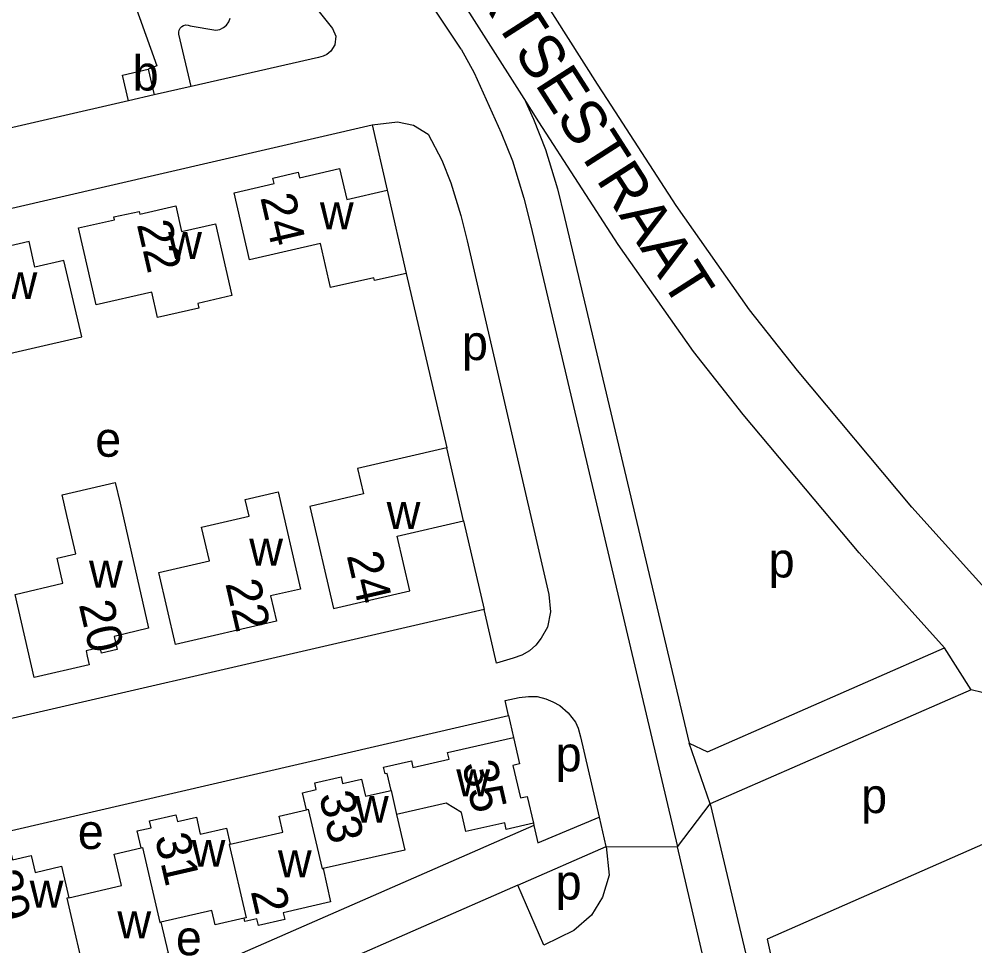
# Model space of a CAD drawing. Extents: x 155696 to 157795, y 382328 to 384028.
# Drawn here: x 157175.4 to 157284.9, y 383600.1 to 383706.4 of the extents above; entities that cross this region are included whole.
import ezdxf

# ---------------------------------------------------------------- set-up
doc = ezdxf.new("R2010")
doc.units = 0
for name, color, linetype in [('BLT_Basislijn', 7, 'Continuous'), ('BLT_Bebouwing', 7, 'Continuous'), ('BLT_Centroide', 7, 'Continuous'), ('BLT_Huisnummer', 7, 'Continuous'), ('BLT_Huisnummer_ tussenligend', 7, 'Continuous'), ('BLT_Onderverdeling_panden', 7, 'Continuous'), ('BLT_Straatnaam', 7, 'Continuous'), ('BLT_Vlakafsluiter', 7, 'Continuous')]:
    doc.layers.add(name, color=color, linetype=linetype)

msp = doc.modelspace()

# ---------------------------------------------------------------- linework, layer by layer
at = {"layer": 'BLT_Basislijn'}
for p, q in [((157284.5, 383629.47), (157281.44, 383634.3)), ((157232.55, 383607.09), (157242.66, 383611.51)), ((157242.66, 383611.51), (157243.02, 383608.23)), ((157243.02, 383608.23), (157242.24, 383605.72)), ((157232.55, 383607.09), (157208.37, 383596.51)), ((157242.24, 383605.72), (157241.01, 383603.63)), ((157241.01, 383603.63), (157238.96, 383601.9)), ((157238.96, 383601.9), (157235.55, 383600.22))]:
    msp.add_line(p, q, dxfattribs=at)
for points in [[(157233.26, 383697.28), (157220.49, 383717.4), (157211.23, 383731.78), (157206.89, 383740.5)], [(157187.92, 383696.99), (157141.96, 383686.41), (157131.62, 383731.15)], [(157226.05, 383702.9), (157219.52, 383712.77), (157213.71, 383719.96)], [(157186.26, 383719.39), (157186.7, 383718.93), (157186.34, 383717.73), (157186.19, 383716.57), (157186.23, 383715.39), (157186.47, 383714.16), (157191.17, 383700.99), (157190.18, 383700.64)], [(157200.69, 383717.82), (157206.91, 383710.81), (157211.31, 383705.3), (157211.69, 383704.41), (157211.59, 383703.4), (157211.14, 383702.68)], [(157242.84, 383697.16), (157241.7, 383698.91), (157233.51, 383711.82)], [(157195.1, 383698.65), (157193.71, 383704.62), (157193.7, 383704.86), (157193.74, 383705.09), (157193.85, 383705.32), (157194.04, 383705.51), (157194.23, 383705.62), (157194.49, 383705.69), (157194.78, 383705.68), (157194.99, 383705.6), (157197.95, 383705.08), (157198.41, 383705.19), (157198.81, 383705.4), (157199.15, 383705.68), (157199.43, 383706.07), (157199.6, 383706.47)], [(157211.14, 383702.68), (157210.66, 383702.29), (157210.24, 383702.12), (157209.71, 383701.97)], [(157226.05, 383702.9), (157227.55, 383700.2), (157230.66, 383693.33), (157231.96, 383690.1), (157233.25, 383685.84), (157234.03, 383682.67), (157250.87, 383611.5)], [(157209.71, 383701.97), (157195.1, 383698.65)], [(157195.1, 383698.65), (157190.88, 383697.68)], [(157233.26, 383697.28), (157234.34, 383694.9), (157235.74, 383691.43), (157237.11, 383686.9), (157237.92, 383683.61), (157252.18, 383623.35)], [(157281.44, 383634.3), (157271.68, 383645.19), (157258.39, 383661.03), (157252.68, 383668.25), (157244.07, 383680.52), (157234.97, 383694.6), (157233.26, 383697.28)], [(157290.02, 383636.87), (157288.12, 383638.83), (157277.72, 383650.43), (157264.59, 383666.09), (157259.09, 383673.04), (157250.71, 383684.99), (157242.84, 383697.16)], [(157215.85, 383694.24), (157218.76, 383694.59), (157220.6, 383694.19), (157222.27, 383693.19), (157223.84, 383690.19), (157224.88, 383687.61), (157226.01, 383683.86), (157226.73, 383680.93), (157236.12, 383640.42), (157236.3, 383638.41), (157235.97, 383636.68), (157235.23, 383635.41), (157234.63, 383634.6), (157233.89, 383633.96), (157233.03, 383633.44), (157232.02, 383633.1), (157230.1, 383632.55), (157228.68, 383638.7)], [(157143.98, 383677.64), (157215.85, 383694.24)], [(157215.85, 383694.24), (157217.56, 383686.74)], [(157219.75, 383677.22), (157224.4, 383657.21)], [(157226.33, 383648.86), (157228.68, 383638.7)], [(157228.68, 383638.7), (157156.81, 383622.1)], [(157252.18, 383623.35), (157254.28, 383622.37), (157281.44, 383634.3)], [(157284.5, 383629.47), (157254.58, 383616.41)], [(157312.33, 383601.15), (157310.1, 383603.15), (157289.93, 383624.65), (157285.78, 383629.16), (157284.5, 383629.47)], [(157231.49, 383626.52), (157231.12, 383628.25), (157232.7, 383628.61), (157233.78, 383628.73), (157234.78, 383628.7), (157235.77, 383628.44), (157236.58, 383628.12), (157237.38, 383627.67), (157238.34, 383626.83), (157239.15, 383625.77), (157239.47, 383625.1), (157239.75, 383624.09), (157241.88, 383614.89)], [(157159.62, 383609.92), (157231.49, 383626.52)], [(157231.49, 383626.52), (157232.06, 383624.03)], [(157254.58, 383616.41), (157265.55, 383570.16), (157266.56, 383565.8)], [(157234.4, 383613.91), (157234.86, 383611.95), (157241.88, 383614.89)], [(157241.88, 383614.89), (157242.65, 383611.51)], [(157308.66, 383597.41), (157292.13, 383614.53), (157261.12, 383600.89), (157267.05, 383574.43)], [(157234.4, 383613.91), (157165.65, 383583.84), (157164.91, 383587.02)], [(157234.34, 383614.18), (157234.4, 383613.91)], [(157343.69, 383231.89), (157341.11, 383231.75), (157339.69, 383232.44), (157338.68, 383233.57), (157337.75, 383235.4), (157324.13, 383294.34), (157315.46, 383331.86), (157299.82, 383399.57), (157277.88, 383494.57), (157267.86, 383537.93), (157256.53, 383587.01), (157250.87, 383611.5)], [(157235.55, 383600.22), (157232.55, 383607.09)]]:
    msp.add_lwpolyline(points, dxfattribs=at)
at = {"layer": 'BLT_Bebouwing'}
msp.add_line((157190.88, 383697.68), (157187.92, 383696.99), dxfattribs=at)
for points in [[(157187.92, 383696.99), (157187.23, 383699.94), (157190.18, 383700.64)], [(157190.18, 383700.64), (157190.88, 383697.68)], [(157219.75, 383677.22), (157216.11, 383676.39), (157216.04, 383676.7), (157211.1, 383675.59), (157209.95, 383680.63), (157201.81, 383678.76), (157200.04, 383686.46), (157204.64, 383687.51), (157204.49, 383688.15), (157207.37, 383688.82), (157207.52, 383688.18), (157212.13, 383689.23), (157212.95, 383685.67), (157217.56, 383686.74)], [(157217.56, 383686.74), (157219.75, 383677.22)], [(157224.4, 383657.21), (157214.17, 383654.85), (157214.85, 383651.93), (157208.71, 383650.51), (157211.41, 383638.82), (157220.18, 383640.84), (157218.73, 383647.11), (157226.33, 383648.86)], [(157226.33, 383648.86), (157224.4, 383657.21)], [(157207.65, 383641.03), (157204.22, 383640.24), (157204.89, 383637.35), (157193.32, 383634.67), (157191.42, 383642.92), (157197.2, 383644.25), (157196.31, 383648.11), (157201.75, 383649.37), (157201.3, 383651.3), (157205.07, 383652.17), (157207.65, 383641.03)], [(157218.02, 383617.93), (157217.56, 383619.89), (157217.36, 383619.84), (157217.17, 383620.62), (157220.35, 383621.34), (157220.53, 383620.56), (157224.67, 383621.52), (157224.48, 383622.29), (157232.06, 383624.03)], [(157232.06, 383624.03), (157232.76, 383621), (157231.97, 383620.82), (157232.84, 383617.08), (157233.63, 383617.26), (157234.34, 383614.18)], [(157208.32, 383615.73), (157207.87, 383617.68), (157209.45, 383618.05), (157209.27, 383618.83), (157212.29, 383619.52), (157212.47, 383618.74), (157214.63, 383619.24), (157215.08, 383617.29), (157218.02, 383617.93)], [(157199.59, 383611.77), (157205.63, 383613.16), (157205.21, 383615.01), (157208.32, 383615.73)], [(157234.34, 383614.18), (157231.23, 383613.47), (157231.06, 383614.25), (157226.59, 383613.25), (157226.11, 383615.41), (157224.33, 383616.5), (157218.65, 383615.19)], [(157189.39, 383611.36), (157188.94, 383613.31), (157190.53, 383613.67), (157190.35, 383614.45), (157193.37, 383615.15), (157193.55, 383614.37), (157195.71, 383614.87), (157196.16, 383612.92), (157199.17, 383613.62), (157199.59, 383611.77)], [(157218.65, 383615.19), (157219.6, 383611.11), (157210.23, 383608.99)], [(157181.08, 383605.64), (157187.12, 383607.04), (157186.29, 383610.64), (157189.39, 383611.36)], [(157170.47, 383606.99), (157170.02, 383608.94), (157171.61, 383609.3), (157171.43, 383610.08), (157174.45, 383610.78), (157174.63, 383610), (157176.78, 383610.5), (157177.23, 383608.55), (157180.24, 383609.25), (157181.08, 383605.64)], [(157210.23, 383608.99), (157211.09, 383605.18), (157205.66, 383603.93), (157205.84, 383603.15), (157202.82, 383602.45), (157202.64, 383603.23), (157201.27, 383602.91), (157201.18, 383603.3)], [(157201.18, 383603.3), (157197.86, 383602.54), (157197.47, 383604.19), (157191.64, 383602.84)], [(157191.64, 383602.84), (157192.46, 383599.29), (157189.16, 383598.53), (157189.61, 383596.58), (157187.46, 383596.08), (157187.64, 383595.3), (157184.62, 383594.6), (157184.44, 383595.38), (157183.07, 383595.07), (157182.98, 383595.46)]]:
    msp.add_lwpolyline(points, dxfattribs=at)
for points in [[(157197.91, 383682.91), (157199.78, 383674.67), (157195.88, 383673.78), (157196.01, 383673.24), (157191.27, 383672.16), (157190.6, 383675.08), (157184.22, 383673.63), (157182.22, 383682.42), (157186.33, 383683.35), (157186.26, 383683.68), (157189.14, 383684.32), (157189.22, 383684.01), (157193.34, 383684.95), (157194, 383682.02)], [(157182.57, 383669.94), (157180.54, 383678.71), (157177.21, 383677.94), (157176.53, 383680.86), (157164.84, 383678.16), (157166.87, 383669.39), (157170.76, 383670.29), (157171.44, 383667.37)], [(157186.97, 383650.88), (157190.24, 383636.53), (157186.3, 383635.6), (157186.63, 383634.1), (157184.83, 383633.7), (157184.69, 383634.32), (157183.07, 383633.94), (157183.21, 383633.34), (157183.43, 383632.35), (157177.12, 383630.89), (157174.93, 383640.42), (157180.4, 383641.69), (157179.74, 383644.59), (157181.88, 383645.08), (157180.87, 383649.47), (157180.33, 383651.85), (157186.42, 383653.25)]]:
    msp.add_lwpolyline(points, close=True, dxfattribs=at)
at = {"layer": 'BLT_Onderverdeling_panden'}
msp.add_line((157218.02, 383617.93), (157218.65, 383615.19), dxfattribs=at)
for points in [[(157208.32, 383615.73), (157208.53, 383615.78), (157210.11, 383608.96), (157210.23, 383608.99)], [(157189.39, 383611.36), (157189.53, 383611.39), (157191.52, 383602.82), (157191.64, 383602.84)], [(157199.59, 383611.77), (157199.46, 383611.74), (157201.4, 383603.35), (157201.18, 383603.3)], [(157181.08, 383605.64), (157180.87, 383605.59), (157183.2, 383595.51), (157182.98, 383595.46)]]:
    msp.add_lwpolyline(points, dxfattribs=at)
at = {"layer": 'BLT_Vlakafsluiter'}
for p, q in [((157254.58, 383616.41), (157252.18, 383623.35)), ((157250.87, 383611.5), (157254.58, 383616.41)), ((157242.65, 383611.51), (157250.87, 383611.5))]:
    msp.add_line(p, q, dxfattribs=at)

# ---------------------------------------------------------------- texts
at = {"layer": 'BLT_Centroide'}
for s, p in [('b', (157188.41, 383698.18)), ('w', (157209.87, 383682.28)), ('w', (157192.48, 383678.88)), ('w', (157173.62, 383674.28)), ('p', (157226.15, 383667.28)), ('e', (157184.12, 383656.2)), ('w', (157217.52, 383647.92)), ('w', (157201.77, 383643.72)), ('p', (157261.3, 383642.36)), ('w', (157183.41, 383641.2)), ('p', (157236.89, 383620.13)), ('w', (157225.5, 383617.28)), ('p', (157271.9, 383615.35)), ('w', (157213.89, 383614.25)), ('e', (157182.12, 383611.23)), ('w', (157195.17, 383609.2)), ('w', (157205.06, 383608)), ('p', (157236.89, 383605.44)), ('w', (157176.61, 383604.52)), ('w', (157186.66, 383601)), ('e', (157193.37, 383599.05))]:
    msp.add_text(s, height=4, dxfattribs=at).set_placement(p)
at = {"layer": 'BLT_Huisnummer'}
for s, rotation, p in [('24', 283.0057, (157203.02, 383685.93)), ('22', 283.0057, (157188.87, 383682.85)), ('24', 283.0069, (157212.92, 383644.89)), ('22', 283.007, (157199.01, 383641.69)), ('20', 283.0075, (157182.22, 383639.28)), ('35', 283.0063, (157226.13, 383620.93)), ('29', 283.0063, (157171.6, 383608.4)), ('2', 283.0063, (157201.92, 383606.39))]:
    msp.add_text(s, height=4, rotation=rotation, dxfattribs=at).set_placement(p)
at = {"layer": 'BLT_Huisnummer_ tussenligend'}
for s, p in [('33', (157209.74, 383617.41)), ('31', (157190.92, 383612.6))]:
    msp.add_text(s, height=4, rotation=283.0063, dxfattribs=at).set_placement(p)
at = {"layer": 'BLT_Straatnaam'}
msp.add_text('SLIFFERTSESTRAAT', height=5, rotation=302.6652, dxfattribs=at).set_placement((157214.99, 383729.25))

doc.saveas('drawing.dxf')
